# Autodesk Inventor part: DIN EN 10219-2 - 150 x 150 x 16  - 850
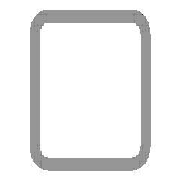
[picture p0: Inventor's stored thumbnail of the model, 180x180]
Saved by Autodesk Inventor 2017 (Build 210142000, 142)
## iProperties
IsCustomPart: 1
Created: 2017-11
Part Number: DIN EN 10219-2 - 150 x 150 x 16  - 850
Material: Steel, Mild
Description: Cold formed welded structural hollow sections of non-alloy and fine grain structural steel
Document SubType Name: Modeling
Standard: DIN
Designer: iusti
Standard Revision: 2006-07
Standards Organization: DIN
Language: en-US
Size Designation: 150 x 150 x 16
Categories: <MemberInstance><Categories><Category DisplayName="Structural Shapes" InternalName="089c4875-fa83-4c05-b084-43b9cc11f5ed" Mnemonic="GRDR"><CategoryParameter Dis
Stock Number: 150 x 150 x 16
Mass: 49891.9 g
Surface Area: 8094.11 cm^2
Volume: 6355.65 cm^3
Density: 7.85 g/cm^3
Appearance: Semi-Polished
_CCFamilyMember: 76
_CCFamilyDisplayName: DIN EN 10219-2 (Square Hollow Section - Cold Formed) - Cold formed welded structural hollow sections of non-alloy and fine grain structural steel
_FrameMemberDoc: Frame Member File
_Version: 15.0.0
_GetPNFromCC: 1
G_L: 850.000 mm
G_W: 150.000 mm
G_H: 150.000 mm
+7D1ACB6B-707D-4FA8-9414-CBA81EBC054A+CUTDETAIL1: Cut
+A291D230-5091-4B43-A225-1E0F01C6EB95+CUTDETAIL2: Cut
Author: iusti
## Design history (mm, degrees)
node "Start plane"
node "End plane"
sketch "Sketch"
  geometry: L1 (-75, -27)-(-75, 27); L2 (-27, 75)-(27, 75); L3 (75, 27)-(75, -27); L4 (27, -75)-(-27, -75); L5 (-27, 59)-(27, 59); L6 (59, 27)-(59, -27); L7 (27, -59)-(-27, -59); L8 (-59, -27)-(-59, 27); L9 (0, 118.918)-(0, -118.918) reference; L10 (-118.918, 0)-(118.918, 0) reference; A1 r 48 centre (-27, -27) between (-75, -27) and (-27, -75); A2 r 48 centre (-27, 27) between (-27, 75) and (-75, 27); A3 r 48 centre (27, 27) between (75, 27) and (27, 75); A4 r 48 centre (27, -27) between (27, -75) and (75, -27); A5 r 32 centre (-27, 27) between (-27, 59) and (-59, 27); A6 r 32 centre (27, 27) between (59, 27) and (27, 59); A7 r 32 centre (27, -27) between (27, -59) and (59, -27); A8 r 32 centre (-27, -27) between (-59, -27) and (-27, -59)
  constraints: 16 end point, 16 point on circle, 8 centre point, 8 tangent, 4 parallel, 3 equal radius, 2 perpendicular, 7 other
  dimensions: "d7" = 48 radius of A1 (= G_IR); "d10" = 150 distance between parallel lines of L2 L4 (= G_H); "d11" = 150 distance between parallel lines of L1 L3 (= G_W); "d12" = 16 distance between parallel lines of L3 L6 (= G_T); "d15" = 75 distance between parallel lines of L2 L10 (= 0.5 x d10); "d16" = 75 distance between parallel lines of L9 L3 (= 0.5 x d11)
extrude "Body" new body sketch "Sketch" stored distance "d3" = 850 (= G_L); taper "d4" = 0 deg
node "Driven Length"
  sketch "Sketch3"
    geometry: L1 (0, 0)-(10, 0) reference
    constraints: 2 end point, 1 horizontal
  workplane "Work Plane3"
  sketch "Sketch4"
    geometry: L1 (-2, 75)-(12, 75) reference; L2 (-2, 925)-(12, 925) reference
    dimensions: "d18" = 850 distance between parallel lines of L1 L2 (derived)
workplane "Work Plane4"
split "Split1"
workplane "Work Plane5"
split "Split2"
body "Solid1"
other parameters: "G_W" = 150 [user parameter; used in 1 equation term], "G_H" = 150 [user parameter; used in 1 equation term], "G_T" = 16 [user parameter; used in 1 equation term], "G_IR" = 48 [user parameter; used in 1 equation term], "G_L" = 850 (= d18) [user parameter; used in 1 equation term], "G_OFFSET_START" = -75 [user parameter; used in 1 equation term], "G_OFFSET_END" = -75 [user parameter; used in 1 equation term], "d13" = 75 (= -G_OFFSET_START), "d14" = 925 (= G_OFFSET_END + B_L), "d17" = 90 deg
